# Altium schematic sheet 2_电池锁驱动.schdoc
size 309 x 223 mm; Symbol: Sheet-Symbol_A4; Device: Sheet-Symbol_A4; Company: 嘉立创EDA; Version: V1.0; Page Size: A4; @Project Name: 共享电动车中控; @Page Count: 11; @Update Date: 2024-11-20; @Create Date: 2024-09-26; @Schematic Name: SCH; @Page No: 2; @Page Name: 电池锁驱动; @Board Name: STM32F103C8T6; @Create Time: 02:39:01; @Update Time: 13:25:36
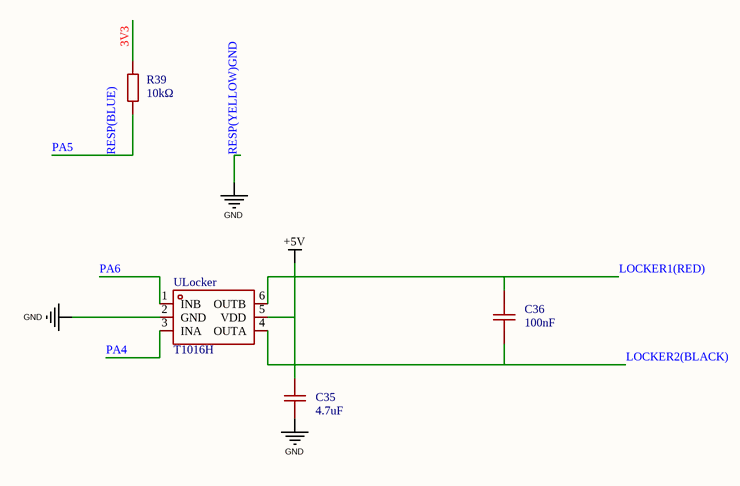
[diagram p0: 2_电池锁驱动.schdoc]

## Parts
C35  4.7uF  [C0805]  (value not drawn)
C36  100nF  [C0805]  (value not drawn)
R39  10kΩ  [R0805]
ULocker  T1016H  [SOT-23-6_L2.9-W1.7-P0.95-LS2.8-BL]  (value not drawn)

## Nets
+5V: C35.2 ULocker.5(VDD)
RESP(YELLOW)GND: C35.1 ULocker.2(GND)  [also labelled GND]
3V3: R39.1
LOCKER1(RED): C36.2 ULocker.6(OUTB)
LOCKER2(BLACK): C36.1 ULocker.4(OUTA)
PA4: ULocker.3(INA)
PA5: R39.2  [also labelled RESP(BLUE)]
PA6: ULocker.1(INB)

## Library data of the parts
C35 = CL21A475KAQNNNE: 容值:4.7uF;精度:±10%;额定电压:25V;材质(温度系数):X5R;; Manufacturer: SAMSUNG(三星); Symbol: CL10A475KP8NNNC; Add into BOM: yes; Tolerance: ±10%; Voltage Rated: 25V; Temperature Coefficient: X5R
C36 = CC0805KRX7R9BB104: 容值:100nF;精度:±10%;额定电压:50V;材质(温度系数):X7R;; Manufacturer: YAGEO(国巨); Symbol: CL10B104KB8NNNC; Add into BOM: yes; Tolerance: ±10%; Voltage Rated: 50V; Temperature Coefficient: X7R
R39 = 0805W8F1002T5E_C17414: 电阻类型:厚膜电阻;阻值:10kΩ;精度:±1%;功率:125mW;最大工作电压:150V;温度系数:±100ppm/℃;; Manufacturer: UNI-ROYAL(厚声); Symbol: RC0402FR-0710KL; Add into BOM: yes; Tolerance: ±1%; Power(Watts): 125mW; Overload Voltage (Max): 150V
ULocker = T1016H: Manufacturer: FM(富满); Add into BOM: yes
